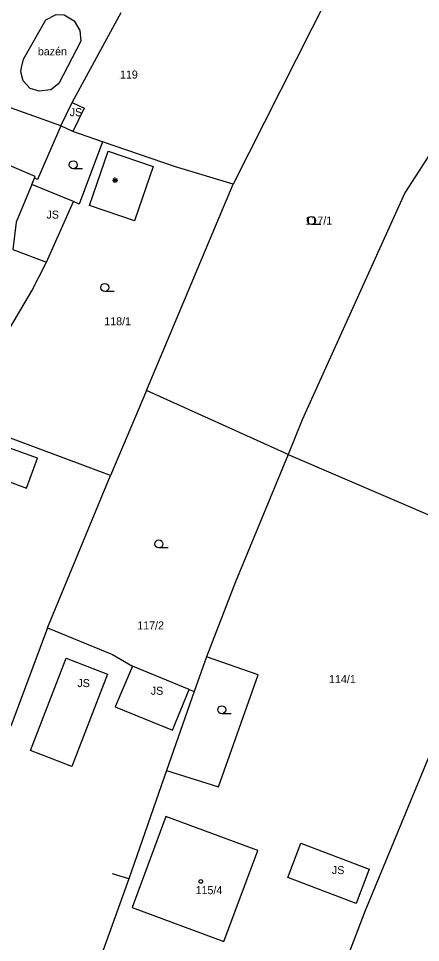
# Model space of a CAD drawing. Extents: x -836739 to -835945, y -1070775 to -1070126.
# Drawn here: x -836495.7 to -836458, y -1070449 to -1070362.4 of the extents above; entities that cross this region are included whole.
import ezdxf

# ---------------------------------------------------------------- set-up
doc = ezdxf.new("R2010")
doc.units = 0
for name, color, linetype in [('BodPole_mer', 7, 'Continuous'), ('Budovy_hranice', 7, 'Continuous'), ('Budovy_kody', 7, 'Continuous'), ('OstPloch_hranice', 7, 'Continuous'), ('OstPloch_kody', 7, 'Continuous'), ('RuianPar_popis', 7, 'Continuous'), ('Stavby_hr_stav', 7, 'Continuous'), ('Stavby_kody', 7, 'Continuous'), ('Stavby_linie', 7, 'Continuous'), ('Vodstvo_hranice', 7, 'Continuous'), ('Vodstvo_kody', 7, 'Continuous')]:
    doc.layers.add(name, color=color, linetype=linetype)

msp = doc.modelspace()

# ---------------------------------------------------------------- linework, layer by layer
at = {"layer": 'BodPole_mer'}
for p, q in [((-836493.11, -1070362.5), (-836493.11, -1070362.5)), ((-836490.44, -1070362.57), (-836490.44, -1070362.57)), ((-836489.91, -1070363.49), (-836489.91, -1070363.49)), ((-836489.84, -1070364.5), (-836489.84, -1070364.5)), ((-836495.21, -1070366.18), (-836495.21, -1070366.18)), ((-836495.45, -1070367.35), (-836495.45, -1070367.35)), ((-836495.38, -1070366.95), (-836495.38, -1070366.95)), ((-836495.24, -1070368.2), (-836495.24, -1070368.2)), ((-836491.89, -1070368.47), (-836491.89, -1070368.47)), ((-836494.57, -1070368.91), (-836494.57, -1070368.91)), ((-836493.74, -1070369.18), (-836493.74, -1070369.18)), ((-836492.64, -1070369.05), (-836492.64, -1070369.05)), ((-836490.64, -1070370.23), (-836490.64, -1070370.23)), ((-836489.5, -1070370.76), (-836489.5, -1070370.76)), ((-836491.71, -1070372.41), (-836491.71, -1070372.41)), ((-836490.58, -1070372.96), (-836490.58, -1070372.96)), ((-836487.78, -1070373.92), (-836487.78, -1070373.92)), ((-836487.25, -1070374.79), (-836487.25, -1070374.79)), ((-836483.05, -1070376.23), (-836483.05, -1070376.23)), ((-836480.96, -1070376.27), (-836480.96, -1070376.27)), ((-836494.43, -1070377.92), (-836494.43, -1070377.92)), ((-836494.18, -1070377.33), (-836494.18, -1070377.33)), ((-836494.11, -1070377.17), (-836494.11, -1070377.17)), ((-836493.88, -1070377.44), (-836493.88, -1070377.44)), ((-836475.54, -1070377.9), (-836475.54, -1070377.9)), ((-836459.45, -1070378.71), (-836459.45, -1070378.71)), ((-836490.52, -1070379.52), (-836490.52, -1070379.52)), ((-836489.97, -1070379.76), (-836489.97, -1070379.76)), ((-836489, -1070379.89), (-836489, -1070379.89)), ((-836484.8, -1070381.33), (-836484.8, -1070381.33)), ((-836493.04, -1070385.21), (-836493.04, -1070385.21)), ((-836494.43, -1070387.9), (-836494.43, -1070387.9)), ((-836464.64, -1070390.16), (-836464.64, -1070390.16)), ((-836483.68, -1070397.24), (-836483.68, -1070397.24)), ((-836469.09, -1070399.98), (-836469.09, -1070399.98)), ((-836493.9, -1070403.58), (-836493.9, -1070403.58)), ((-836470.4, -1070403.24), (-836470.4, -1070403.24)), ((-836487.03, -1070405.19), (-836487.03, -1070405.19)), ((-836494.91, -1070406.38), (-836494.91, -1070406.38)), ((-836475.34, -1070415.17), (-836475.34, -1070415.17)), ((-836492.95, -1070419.48), (-836492.95, -1070419.48)), ((-836486.87, -1070421.98), (-836486.87, -1070421.98)), ((-836491.2, -1070422.33), (-836491.2, -1070422.33)), ((-836478.04, -1070422.2), (-836478.04, -1070422.2)), ((-836487.32, -1070423.83), (-836487.32, -1070423.83)), ((-836484.98, -1070423.09), (-836484.98, -1070423.09)), ((-836473.21, -1070423.9), (-836473.21, -1070423.9)), ((-836479.68, -1070425.25), (-836479.68, -1070425.25)), ((-836479.19, -1070425.44), (-836479.19, -1070425.44)), ((-836486.62, -1070426.9), (-836486.62, -1070426.9)), ((-836481.24, -1070429.09), (-836481.24, -1070429.09)), ((-836494.55, -1070430.98), (-836494.55, -1070430.98)), ((-836490.67, -1070432.48), (-836490.67, -1070432.48)), ((-836481.8, -1070432.85), (-836481.8, -1070432.85)), ((-836476.93, -1070434.4), (-836476.93, -1070434.4)), ((-836481.87, -1070437.18), (-836481.87, -1070437.18)), ((-836473.24, -1070440.36), (-836473.24, -1070440.36)), ((-836469.19, -1070439.66), (-836469.19, -1070439.66)), ((-836486.87, -1070442.53), (-836486.87, -1070442.53)), ((-836470.42, -1070442.88), (-836470.42, -1070442.88)), ((-836462.79, -1070442.11), (-836462.79, -1070442.11)), ((-836485.34, -1070443), (-836485.34, -1070443)), ((-836464.02, -1070445.33), (-836464.02, -1070445.33)), ((-836485.02, -1070445.71), (-836485.02, -1070445.71)), ((-836463.2, -1070446.07), (-836463.2, -1070446.07)), ((-836476.42, -1070448.9), (-836476.42, -1070448.9))]:
    msp.add_line(p, q, dxfattribs=at)
at = {"layer": 'Budovy_hranice'}
for p, q in [((-836491.71, -1070372.41), (-836506.52, -1070367.12)), ((-836491.71, -1070372.41), (-836493.88, -1070377.44)), ((-836494.11, -1070377.17), (-836499.7, -1070374.83)), ((-836494.18, -1070377.33), (-836494.11, -1070377.17)), ((-836493.88, -1070377.44), (-836494.18, -1070377.33))]:
    msp.add_line(p, q, dxfattribs=at)
for points in [[(-836483.05, -1070376.23), (-836484.8, -1070381.33), (-836489, -1070379.89), (-836487.25, -1070374.79), (-836483.05, -1070376.23)], [(-836476.42, -1070448.9), (-836473.24, -1070440.36), (-836481.87, -1070437.18), (-836485.02, -1070445.71), (-836476.42, -1070448.9)]]:
    msp.add_lwpolyline(points, dxfattribs=at)
at = {"layer": 'Budovy_kody'}
for p, q in [((-836486.86, -1070377.53), (-836486.36, -1070377.53)), ((-836486.433, -1070377.707), (-836486.787, -1070377.353)), ((-836486.433, -1070377.353), (-836486.787, -1070377.707)), ((-836486.61, -1070377.78), (-836486.61, -1070377.28))]:
    msp.add_line(p, q, dxfattribs=at)
msp.add_circle((-836478.58, -1070443.26), 0.175, dxfattribs=at)
at = {"layer": 'OstPloch_hranice'}
for p, q in [((-836494.43, -1070377.92), (-836494.18, -1070377.33)), ((-836479.68, -1070425.25), (-836479.19, -1070425.44))]:
    msp.add_line(p, q, dxfattribs=at)
at = {"layer": 'OstPloch_kody'}
for p, q in [((-836489.665, -1070376.45), (-836490.54, -1070376.45)), ((-836467.325, -1070381.67), (-836468.2, -1070381.67)), ((-836486.705, -1070387.95), (-836487.58, -1070387.95)), ((-836481.635, -1070411.99), (-836482.51, -1070411.99)), ((-836475.745, -1070427.54), (-836476.62, -1070427.54))]:
    msp.add_line(p, q, dxfattribs=at)
for centre in [(-836490.54, -1070376.075), (-836468.2, -1070381.295), (-836487.58, -1070387.575), (-836482.51, -1070411.615), (-836476.62, -1070427.165)]:
    msp.add_ellipse(centre, major_axis=(0.375, 0), ratio=0.999999, dxfattribs=at)
at = {"layer": 'RuianPar_popis'}
for p, q in [((-836486.16, -1070367.99), (-836486.16, -1070367.99)), ((-836468.77, -1070381.68), (-836468.77, -1070381.68)), ((-836487.63, -1070391.12), (-836487.63, -1070391.12)), ((-836484.54, -1070419.63), (-836484.54, -1070419.63)), ((-836466.56, -1070424.67), (-836466.56, -1070424.67)), ((-836479.07, -1070444.45), (-836479.07, -1070444.45))]:
    msp.add_line(p, q, dxfattribs=at)
at = {"layer": 'Stavby_hr_stav'}
for points in [[(-836491.71, -1070372.41), (-836490.64, -1070370.23), (-836489.5, -1070370.76), (-836490.58, -1070372.96), (-836491.71, -1070372.41)], [(-836494.43, -1070377.92), (-836495.9, -1070381.44), (-836496.2, -1070384.02), (-836493.04, -1070385.21), (-836490.52, -1070379.52), (-836494.43, -1070377.92)], [(-836498.42, -1070401.95), (-836499.43, -1070404.75), (-836494.91, -1070406.38), (-836493.9, -1070403.58), (-836498.42, -1070401.95)], [(-836494.55, -1070430.98), (-836491.2, -1070422.33), (-836487.32, -1070423.83), (-836490.67, -1070432.48), (-836494.55, -1070430.98)], [(-836479.68, -1070425.25), (-836484.98, -1070423.09), (-836486.62, -1070426.9), (-836481.24, -1070429.09), (-836479.68, -1070425.25)], [(-836470.42, -1070442.88), (-836469.19, -1070439.66), (-836462.79, -1070442.11), (-836464.02, -1070445.33), (-836470.42, -1070442.88)]]:
    msp.add_lwpolyline(points, dxfattribs=at)
at = {"layer": 'Stavby_linie'}
for p, q in [((-836464.69, -1070356.37), (-836475.54, -1070377.9)), ((-836490.64, -1070370.23), (-836486.05, -1070361.8)), ((-836470.4, -1070403.24), (-836449.39, -1070412.25)), ((-836492.95, -1070419.48), (-836487.03, -1070405.19)), ((-836492.95, -1070419.48), (-836496.39, -1070428.69)), ((-836492.95, -1070419.48), (-836486.87, -1070421.98)), ((-836486.87, -1070421.98), (-836484.98, -1070423.09))]:
    msp.add_line(p, q, dxfattribs=at)
for points in [[(-836451.09, -1070365.35), (-836457.52, -1070375.69), (-836459.45, -1070378.71), (-836464.64, -1070390.16), (-836469.09, -1070399.98), (-836470.4, -1070403.24)], [(-836483.68, -1070397.24), (-836475.54, -1070377.9), (-836480.96, -1070376.27), (-836487.78, -1070373.92), (-836490.58, -1070372.96)], [(-836487.78, -1070373.92), (-836489.97, -1070379.76), (-836490.52, -1070379.52)], [(-836500.91, -1070400.2), (-836499.66, -1070397.56), (-836496.79, -1070391.92), (-836494.43, -1070387.9), (-836493.04, -1070385.21)], [(-836470.4, -1070403.24), (-836483.68, -1070397.24), (-836487.03, -1070405.19), (-836498.55, -1070400.92)], [(-836470.4, -1070403.24), (-836475.34, -1070415.17), (-836478.04, -1070422.2), (-836479.19, -1070425.44), (-836481.8, -1070432.85), (-836476.93, -1070434.4), (-836473.21, -1070423.9), (-836478.04, -1070422.2)], [(-836449.39, -1070412.25), (-836456.32, -1070429.46), (-836463.2, -1070446.07), (-836469.22, -1070461.85), (-836476.75, -1070482.14), (-836479.99, -1070490.54)], [(-836481.8, -1070432.85), (-836485.34, -1070443), (-836486.87, -1070442.53)], [(-836485.34, -1070443), (-836489.31, -1070454.06), (-836495.6, -1070472.71)]]:
    msp.add_lwpolyline(points, dxfattribs=at)
at = {"layer": 'Vodstvo_hranice'}
msp.add_lwpolyline([(-836495.38, -1070366.95), (-836495.21, -1070366.18), (-836493.11, -1070362.5), (-836492.15, -1070362), (-836491.4, -1070362.02), (-836490.44, -1070362.57), (-836489.91, -1070363.49), (-836489.84, -1070364.5), (-836491.89, -1070368.47), (-836492.64, -1070369.05), (-836493.74, -1070369.18), (-836494.57, -1070368.91), (-836495.24, -1070368.2), (-836495.45, -1070367.35), (-836495.38, -1070366.95)], dxfattribs=at)

# ---------------------------------------------------------------- texts
at = {"layer": 'RuianPar_popis'}
for s, p in [('119', (-836486.16, -1070367.99)), ('117/1', (-836468.77, -1070381.68)), ('118/1', (-836487.63, -1070391.12)), ('117/2', (-836484.54, -1070419.63)), ('114/1', (-836466.56, -1070424.67)), ('115/4', (-836479.07, -1070444.45))]:
    msp.add_text(s, height=0.75, dxfattribs=at).set_placement(p)
at = {"layer": 'Stavby_kody'}
for p in [(-836490.87, -1070371.52), (-836493.05, -1070381.12), (-836490.15, -1070425.04), (-836483.27, -1070425.76), (-836466.29, -1070442.57)]:
    msp.add_text('JS', height=0.75, dxfattribs=at).set_placement(p)
at = {"layer": 'Vodstvo_kody'}
msp.add_text('bazén', height=0.75, dxfattribs=at).set_placement((-836493.86, -1070365.82))

doc.saveas('drawing.dxf')
